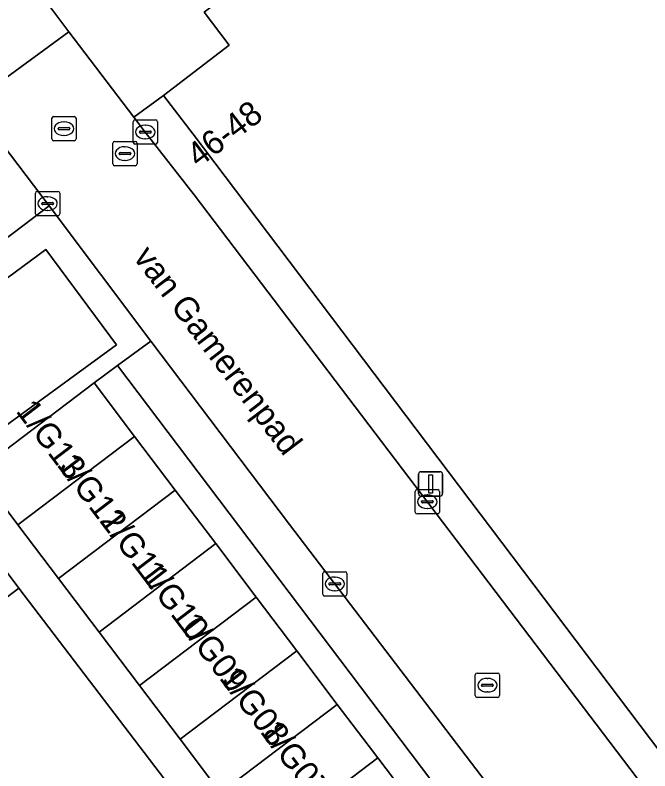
# Model space of a CAD drawing. Extents: x 160030 to 160839, y 385325 to 386450.
# Drawn here: x 160266.91 to 160293.06, y 385935.27 to 385966.37 of the extents above; entities that cross this region are included whole.
import ezdxf

# ---------------------------------------------------------------- set-up
doc = ezdxf.new("R2010")
doc.units = 0
for name, color, linetype in [('IMGEO_Erf', 7, 'Continuous'), ('IMGEO_Groenvoorziening', 7, 'Continuous'), ('IMGEO_Kolk', 7, 'Continuous'), ('IMGEO_Lichtmast', 7, 'Continuous'), ('IMGEO_Openbare_ruimte_label', 7, 'Continuous'), ('IMGEO_Pand', 7, 'Continuous'), ('IMGEO_Pand_nummerreeks', 7, 'Continuous'), ('IMGEO_Rijbaan_lokaal_open', 7, 'Continuous'), ('IMGEO_Rioolput', 7, 'Continuous'), ('IMGEO_Voetpad_open', 7, 'Continuous')]:
    doc.layers.add(name, color=color, linetype=linetype)

msp = doc.modelspace()

# ---------------------------------------------------------------- linework, layer by layer
at = {"layer": 'IMGEO_Erf'}
msp.add_lwpolyline([(160271.131, 385951.947), (160270.16, 385951.238), (160271.83, 385949.032), (160273.5, 385946.826), (160275.171, 385944.62), (160276.841, 385942.414), (160278.511, 385940.208), (160280.181, 385938.002), (160281.852, 385935.796), (160283.522, 385933.59), (160285.192, 385931.384), (160286.862, 385929.178), (160288.533, 385926.972), (160290.203, 385924.766), (160291.873, 385922.56), (160291.96, 385922.629), (160292.815, 385923.307)], close=True, dxfattribs=at)
msp.add_lwpolyline([(160274.513, 385933.022), (160267.063, 385942.785), (160262.194, 385939.095), (160257.405, 385935.465), (160252.615, 385931.834)], dxfattribs=at)
at = {"layer": 'IMGEO_Groenvoorziening'}
for points in [[(160268.311, 385958.528), (160261.172, 385953.121), (160264.176, 385949.153), (160265.353, 385947.599), (160270.16, 385951.238), (160271.131, 385951.947), (160272.504, 385952.949)], [(160271.086, 385952.807), (160265.969, 385949.077), (160263.052, 385952.951), (160268.169, 385956.728)], [(160263.052, 385952.951), (160265.969, 385949.077), (160271.086, 385952.807), (160268.169, 385956.728)]]:
    msp.add_lwpolyline(points, close=True, dxfattribs=at)
at = {"layer": 'IMGEO_Kolk'}
for p, q in [((160271.77, 385961.134), (160271.77, 385961.986)), ((160271.845, 385962.06), (160272.697, 385962.06)), ((160272.258, 385961.84), (160272.283, 385961.84)), ((160272.771, 385961.986), (160272.771, 385961.134)), ((160272.029, 385961.554), (160272.029, 385961.566)), ((160272.072, 385961.603), (160272.47, 385961.603)), ((160272.513, 385961.566), (160272.513, 385961.554)), ((160272.467, 385961.517), (160272.069, 385961.517)), ((160272.281, 385961.28), (160272.256, 385961.28)), ((160272.697, 385961.06), (160271.845, 385961.06)), ((160267.743, 385958.191), (160267.743, 385959.043)), ((160267.818, 385959.117), (160268.67, 385959.117)), ((160268.744, 385959.043), (160268.744, 385958.191)), ((160268.231, 385958.897), (160268.256, 385958.897)), ((160268.002, 385958.611), (160268.002, 385958.623)), ((160268.44, 385958.574), (160268.042, 385958.574)), ((160268.045, 385958.66), (160268.443, 385958.66)), ((160268.486, 385958.623), (160268.486, 385958.611)), ((160268.67, 385958.117), (160267.818, 385958.117)), ((160268.254, 385958.337), (160268.229, 385958.337)), ((160283.391, 385945.917), (160283.391, 385946.769)), ((160283.466, 385946.843), (160284.318, 385946.843)), ((160283.879, 385946.623), (160283.904, 385946.623)), ((160284.392, 385946.769), (160284.392, 385945.917)), ((160283.65, 385946.337), (160283.65, 385946.349)), ((160284.088, 385946.3), (160283.69, 385946.3)), ((160283.693, 385946.386), (160284.091, 385946.386)), ((160284.134, 385946.349), (160284.134, 385946.337)), ((160283.902, 385946.063), (160283.877, 385946.063)), ((160284.318, 385945.843), (160283.466, 385945.843)), ((160279.578, 385942.536), (160279.578, 385943.388)), ((160279.653, 385943.462), (160280.505, 385943.462)), ((160280.066, 385943.242), (160280.091, 385943.242)), ((160280.579, 385943.388), (160280.579, 385942.536)), ((160279.837, 385942.956), (160279.837, 385942.968)), ((160280.275, 385942.919), (160279.877, 385942.919)), ((160279.88, 385943.005), (160280.278, 385943.005)), ((160280.321, 385942.968), (160280.321, 385942.956)), ((160280.089, 385942.682), (160280.064, 385942.682)), ((160280.505, 385942.462), (160279.653, 385942.462))]:
    msp.add_line(p, q, dxfattribs=at)
for points in [[(160271.77, 385961.134), (160271.77, 385961.986)], [(160271.845, 385962.06), (160272.697, 385962.06)], [(160272.771, 385961.986), (160272.771, 385961.134)], [(160272.697, 385961.06), (160271.845, 385961.06)], [(160267.743, 385958.191), (160267.743, 385959.043)], [(160267.818, 385959.117), (160268.67, 385959.117)], [(160268.744, 385959.043), (160268.744, 385958.191)], [(160268.67, 385958.117), (160267.818, 385958.117)], [(160283.391, 385945.917), (160283.391, 385946.769)], [(160283.466, 385946.843), (160284.318, 385946.843)], [(160284.392, 385946.769), (160284.392, 385945.917)], [(160284.318, 385945.843), (160283.466, 385945.843)], [(160279.578, 385942.536), (160279.578, 385943.388)], [(160279.653, 385943.462), (160280.505, 385943.462)], [(160280.579, 385943.388), (160280.579, 385942.536)], [(160280.505, 385942.462), (160279.653, 385942.462)]]:
    msp.add_lwpolyline(points, dxfattribs=at)
for centre, radius, start, end in [((160271.847, 385961.984), 0.0765, 91.552, 178.448), ((160271.847, 385961.984), 0.0765, 91.552, 178.448), ((160272.695, 385961.984), 0.0765, 1.552, 88.448), ((160272.695, 385961.984), 0.0765, 1.552, 88.448), ((160272.069, 385961.563), 0.0403, 85.8775, 175.7526), ((160272.066, 385961.553), 0.0366, 178.938, 274.7102), ((160272.47, 385961.56), 0.043, 264.8664, 352.4533), ((160272.474, 385961.565), 0.0386, 1.7309, 96.639), ((160271.847, 385961.136), 0.0765, 181.552, 268.448), ((160271.847, 385961.136), 0.0765, 181.552, 268.448), ((160272.695, 385961.136), 0.0765, 271.552, 358.448), ((160272.695, 385961.136), 0.0765, 271.552, 358.448), ((160267.82, 385959.041), 0.0765, 91.552, 178.448), ((160267.82, 385959.041), 0.0765, 91.552, 178.448), ((160268.668, 385959.041), 0.0765, 1.552, 88.448), ((160268.668, 385959.041), 0.0765, 1.552, 88.448), ((160268.042, 385958.62), 0.0403, 85.8775, 175.7526), ((160268.039, 385958.61), 0.0366, 178.938, 274.7102), ((160268.443, 385958.617), 0.043, 264.8664, 352.4533), ((160268.447, 385958.622), 0.0386, 1.7309, 96.639), ((160267.82, 385958.193), 0.0765, 181.552, 268.448), ((160267.82, 385958.193), 0.0765, 181.552, 268.448), ((160268.668, 385958.193), 0.0765, 271.552, 358.448), ((160268.668, 385958.193), 0.0765, 271.552, 358.448), ((160283.468, 385946.767), 0.0765, 91.552, 178.448), ((160283.468, 385946.767), 0.0765, 91.552, 178.448), ((160284.316, 385946.767), 0.0765, 1.552, 88.448), ((160284.316, 385946.767), 0.0765, 1.552, 88.448), ((160283.69, 385946.346), 0.0403, 85.8775, 175.7526), ((160283.687, 385946.336), 0.0366, 178.938, 274.7102), ((160284.091, 385946.343), 0.043, 264.8664, 352.4533), ((160284.095, 385946.348), 0.0386, 1.7309, 96.639), ((160283.468, 385945.919), 0.0765, 181.552, 268.448), ((160283.468, 385945.919), 0.0765, 181.552, 268.448), ((160284.316, 385945.919), 0.0765, 271.552, 358.448), ((160284.316, 385945.919), 0.0765, 271.552, 358.448), ((160279.655, 385943.386), 0.0765, 91.552, 178.448), ((160279.655, 385943.386), 0.0765, 91.552, 178.448), ((160280.503, 385943.386), 0.0765, 1.552, 88.448), ((160280.503, 385943.386), 0.0765, 1.552, 88.448), ((160279.877, 385942.965), 0.0403, 85.8775, 175.7526), ((160279.874, 385942.955), 0.0366, 178.938, 274.7102), ((160280.278, 385942.962), 0.043, 264.8664, 352.4533), ((160280.282, 385942.967), 0.0386, 1.7309, 96.639), ((160279.655, 385942.538), 0.0765, 181.552, 268.448), ((160279.655, 385942.538), 0.0765, 181.552, 268.448), ((160280.503, 385942.538), 0.0765, 271.552, 358.448), ((160280.503, 385942.538), 0.0765, 271.552, 358.448)]:
    msp.add_arc(centre, radius, start, end, dxfattribs=at)
for centre, major_axis, ratio, start_param, end_param in [((160272.257, 385961.56), (-0.387, 0.002), 0.722429, 4.712389, 7.853982), ((160272.282, 385961.56), (-0.39, 0.002), 0.717154, 1.570796, 4.712389), ((160268.23, 385958.617), (-0.387, 0.002), 0.722429, 4.712389, 7.853982), ((160268.255, 385958.617), (-0.39, 0.002), 0.717154, 1.570796, 4.712389), ((160283.878, 385946.343), (-0.387, 0.002), 0.722429, 4.712389, 7.853982), ((160283.903, 385946.343), (-0.39, 0.002), 0.717154, 1.570796, 4.712389), ((160280.065, 385942.962), (-0.387, 0.002), 0.722429, 4.712389, 7.853982), ((160280.09, 385942.962), (-0.39, 0.002), 0.717154, 1.570796, 4.712389)]:
    msp.add_ellipse(centre, major_axis=major_axis, ratio=ratio, start_param=start_param, end_param=end_param, dxfattribs=at)
at = {"layer": 'IMGEO_Lichtmast'}
for p, q in [((160283.626, 385947.577), (160284.416, 385947.577)), ((160284.416, 385947.577), (160283.626, 385947.577)), ((160283.526, 385946.677), (160283.526, 385947.477)), ((160283.526, 385947.477), (160283.526, 385946.677)), ((160284.516, 385947.477), (160284.516, 385946.677)), ((160284.516, 385946.677), (160284.516, 385947.477)), ((160284.416, 385946.577), (160283.626, 385946.577)), ((160283.626, 385946.577), (160284.416, 385946.577))]:
    msp.add_line(p, q, dxfattribs=at)
msp.add_lwpolyline([(160283.946, 385947.452), (160284.096, 385947.452), (160284.096, 385946.702), (160283.946, 385946.702), (160283.946, 385947.452)], dxfattribs=at)
for centre, start, end in [((160283.626, 385947.477), 90, 180), ((160283.626, 385947.477), 90, 180), ((160284.416, 385947.477), 0, 90), ((160284.416, 385947.477), 360, 90), ((160283.626, 385946.677), 180, 270), ((160283.626, 385946.677), 180, 270), ((160284.416, 385946.677), 270, 0), ((160284.416, 385946.677), 270, 0)]:
    msp.add_arc(centre, 0.1, start, end, dxfattribs=at)
at = {"layer": 'IMGEO_Pand'}
msp.add_lwpolyline([(160296.888, 385963.664), (160292.909, 385968.884), (160291.169, 385967.555), (160288.295, 385971.358), (160290.035, 385972.688), (160287.372, 385976.172), (160280.698, 385971.072), (160281.211, 385970.387), (160278.649, 385968.442), (160278.135, 385969.119), (160274.691, 385966.501), (160275.731, 385965.132), (160273.026, 385963.07), (160274.238, 385961.479), (160300.528, 385926.728)], dxfattribs=at)
for points in [[(160267.023, 385945.393), (160271.83, 385949.032), (160270.16, 385951.238), (160265.353, 385947.599)], [(160267.023, 385945.393), (160268.694, 385943.187), (160273.5, 385946.826), (160271.83, 385949.032)], [(160262.944, 385948.218), (160258.076, 385944.528), (160262.194, 385939.095), (160267.063, 385942.785), (160265.965, 385944.234), (160264.121, 385946.666)], [(160275.171, 385944.62), (160273.5, 385946.826), (160268.694, 385943.187), (160270.364, 385940.981)], [(160270.364, 385940.981), (160272.034, 385938.775), (160276.841, 385942.414), (160275.171, 385944.62)], [(160272.034, 385938.775), (160273.704, 385936.569), (160278.511, 385940.208), (160276.841, 385942.414)], [(160280.181, 385938.002), (160278.511, 385940.208), (160273.704, 385936.569), (160275.375, 385934.363)], [(160275.375, 385934.363), (160277.045, 385932.157), (160281.852, 385935.796), (160280.181, 385938.002)], [(160277.045, 385932.157), (160278.715, 385929.951), (160283.522, 385933.59), (160281.852, 385935.796)]]:
    msp.add_lwpolyline(points, close=True, dxfattribs=at)
at = {"layer": 'IMGEO_Rijbaan_lokaal_open'}
for points in [[(160264.446, 385963.608), (160265.109, 385962.726), (160266.287, 385963.609), (160269.121, 385965.683), (160268.378, 385966.677)], [(160274.289, 385958.969), (160272.271, 385961.56), (160271.801, 385962.176), (160269.121, 385965.683), (160266.287, 385963.609), (160265.109, 385962.726), (160268.311, 385958.528), (160272.504, 385952.949), (160278.21, 385945.409), (160294.227, 385924.426), (160296.595, 385921.073)], [(160300.632, 385924.328), (160300.493, 385924.507), (160299.426, 385925.902), (160274.289, 385958.969)]]:
    msp.add_lwpolyline(points, dxfattribs=at)
at = {"layer": 'IMGEO_Rioolput'}
for p, q in [((160268.494, 385962.2), (160269.346, 385962.2)), ((160268.419, 385961.274), (160268.419, 385962.126)), ((160268.907, 385961.98), (160268.932, 385961.98)), ((160269.42, 385962.126), (160269.42, 385961.274)), ((160268.678, 385961.694), (160268.678, 385961.706)), ((160269.116, 385961.657), (160268.718, 385961.657)), ((160268.721, 385961.743), (160269.119, 385961.743)), ((160269.162, 385961.706), (160269.162, 385961.694)), ((160268.93, 385961.42), (160268.905, 385961.42)), ((160269.346, 385961.2), (160268.494, 385961.2)), ((160270.931, 385960.249), (160270.931, 385961.101)), ((160271.006, 385961.175), (160271.858, 385961.175)), ((160271.419, 385960.955), (160271.444, 385960.955)), ((160271.932, 385961.101), (160271.932, 385960.249)), ((160271.19, 385960.669), (160271.19, 385960.681)), ((160271.628, 385960.632), (160271.23, 385960.632)), ((160271.233, 385960.718), (160271.631, 385960.718)), ((160271.674, 385960.681), (160271.674, 385960.669)), ((160271.442, 385960.395), (160271.417, 385960.395)), ((160271.858, 385960.175), (160271.006, 385960.175)), ((160285.866, 385938.366), (160285.866, 385939.218)), ((160285.941, 385939.292), (160286.793, 385939.292)), ((160286.867, 385939.218), (160286.867, 385938.366)), ((160286.168, 385938.835), (160286.566, 385938.835)), ((160286.354, 385939.072), (160286.379, 385939.072)), ((160286.125, 385938.786), (160286.125, 385938.798)), ((160286.563, 385938.749), (160286.165, 385938.749)), ((160286.377, 385938.512), (160286.352, 385938.512)), ((160286.609, 385938.798), (160286.609, 385938.786)), ((160286.793, 385938.292), (160285.941, 385938.292))]:
    msp.add_line(p, q, dxfattribs=at)
for points in [[(160268.494, 385962.2), (160269.346, 385962.2)], [(160268.419, 385961.274), (160268.419, 385962.126)], [(160269.42, 385962.126), (160269.42, 385961.274)], [(160269.346, 385961.2), (160268.494, 385961.2)], [(160270.931, 385960.249), (160270.931, 385961.101)], [(160271.006, 385961.175), (160271.858, 385961.175)], [(160271.932, 385961.101), (160271.932, 385960.249)], [(160271.858, 385960.175), (160271.006, 385960.175)], [(160285.866, 385938.366), (160285.866, 385939.218)], [(160285.941, 385939.292), (160286.793, 385939.292)], [(160286.867, 385939.218), (160286.867, 385938.366)], [(160286.793, 385938.292), (160285.941, 385938.292)]]:
    msp.add_lwpolyline(points, dxfattribs=at)
for centre, radius, start, end in [((160268.496, 385962.124), 0.0765, 91.552, 178.448), ((160268.496, 385962.124), 0.0765, 91.552, 178.448), ((160269.344, 385962.124), 0.0765, 1.552, 88.448), ((160269.344, 385962.124), 0.0765, 1.552, 88.448), ((160268.718, 385961.703), 0.0403, 85.8775, 175.7526), ((160268.715, 385961.693), 0.0366, 178.938, 274.7102), ((160269.119, 385961.7), 0.043, 264.8664, 352.4533), ((160269.123, 385961.705), 0.0386, 1.7309, 96.639), ((160268.496, 385961.276), 0.0765, 181.552, 268.448), ((160268.496, 385961.276), 0.0765, 181.552, 268.448), ((160269.344, 385961.276), 0.0765, 271.552, 358.448), ((160269.344, 385961.276), 0.0765, 271.552, 358.448), ((160271.008, 385961.099), 0.0765, 91.552, 178.448), ((160271.008, 385961.099), 0.0765, 91.552, 178.448), ((160271.856, 385961.099), 0.0765, 1.552, 88.448), ((160271.856, 385961.099), 0.0765, 1.552, 88.448), ((160271.23, 385960.678), 0.0403, 85.8775, 175.7526), ((160271.227, 385960.668), 0.0366, 178.938, 274.7102), ((160271.631, 385960.675), 0.043, 264.8664, 352.4533), ((160271.635, 385960.68), 0.0386, 1.7309, 96.639), ((160271.008, 385960.251), 0.0765, 181.552, 268.448), ((160271.008, 385960.251), 0.0765, 181.552, 268.448), ((160271.856, 385960.251), 0.0765, 271.552, 358.448), ((160271.856, 385960.251), 0.0765, 271.552, 358.448), ((160285.943, 385939.216), 0.0765, 91.552, 178.448), ((160285.943, 385939.216), 0.0765, 91.552, 178.448), ((160286.791, 385939.216), 0.0765, 1.552, 88.448), ((160286.791, 385939.216), 0.0765, 1.552, 88.448), ((160286.165, 385938.795), 0.0403, 85.8775, 175.7526), ((160286.57, 385938.797), 0.0386, 1.7309, 96.639), ((160286.162, 385938.785), 0.0366, 178.938, 274.7102), ((160286.566, 385938.792), 0.043, 264.8664, 352.4533), ((160285.943, 385938.368), 0.0765, 181.552, 268.448), ((160285.943, 385938.368), 0.0765, 181.552, 268.448), ((160286.791, 385938.368), 0.0765, 271.552, 358.448), ((160286.791, 385938.368), 0.0765, 271.552, 358.448)]:
    msp.add_arc(centre, radius, start, end, dxfattribs=at)
for centre, major_axis, ratio, start_param, end_param in [((160268.906, 385961.7), (-0.387, 0.002), 0.722429, 4.712389, 7.853982), ((160268.931, 385961.7), (-0.39, 0.002), 0.717154, 1.570796, 4.712389), ((160271.418, 385960.675), (-0.387, 0.002), 0.722429, 4.712389, 7.853982), ((160271.443, 385960.675), (-0.39, 0.002), 0.717154, 1.570796, 4.712389), ((160286.353, 385938.792), (-0.387, 0.002), 0.722429, 4.712389, 7.853982), ((160286.378, 385938.792), (-0.39, 0.002), 0.717154, 1.570796, 4.712389)]:
    msp.add_ellipse(centre, major_axis=major_axis, ratio=ratio, start_param=start_param, end_param=end_param, dxfattribs=at)
at = {"layer": 'IMGEO_Voetpad_open'}
for points in [[(160268.378, 385966.677), (160269.121, 385965.683), (160271.801, 385962.176), (160273.026, 385963.07), (160275.731, 385965.132), (160274.691, 385966.501), (160278.135, 385969.119), (160278.649, 385968.442), (160281.211, 385970.387), (160280.698, 385971.072), (160287.372, 385976.172)], [(160259.939, 385952.187), (160261.172, 385953.121), (160268.311, 385958.528), (160265.109, 385962.726), (160264.446, 385963.608)]]:
    msp.add_lwpolyline(points, dxfattribs=at)
for points in [[(160274.238, 385961.479), (160273.026, 385963.07), (160271.801, 385962.176), (160272.271, 385961.56), (160274.289, 385958.969), (160299.426, 385925.902), (160300.528, 385926.728)], [(160292.815, 385923.307), (160294.227, 385924.426), (160278.21, 385945.409), (160272.504, 385952.949), (160271.131, 385951.947)], [(160277.045, 385932.157), (160275.375, 385934.363), (160273.704, 385936.569), (160272.034, 385938.775), (160270.364, 385940.981), (160268.694, 385943.187), (160267.023, 385945.393), (160265.353, 385947.599), (160264.121, 385946.666), (160265.965, 385944.234), (160267.063, 385942.785), (160274.513, 385933.022), (160275.43, 385931.82), (160283.21, 385921.624), (160284.24, 385920.265), (160285.917, 385918.052), (160287.066, 385918.921), (160285.396, 385921.127), (160283.726, 385923.333), (160282.056, 385925.539), (160280.385, 385927.745), (160278.715, 385929.951)]]:
    msp.add_lwpolyline(points, close=True, dxfattribs=at)

# ---------------------------------------------------------------- texts
at = {"layer": 'IMGEO_Openbare_ruimte_label'}
msp.add_text('van Gamerenpad', height=1, rotation=307.2823, dxfattribs=at).set_placement((160271.742, 385956.395))
at = {"layer": 'IMGEO_Pand_nummerreeks'}
for s, rotation, p in [('46-48', 37.1162, (160274.462, 385960.067)), ('1/G13', 307.3301, (160266.907, 385950.07)), ('1/G12', 307.3301, (160268.59, 385947.863)), ('1/G11', 307.3301, (160270.347, 385945.559)), ('1/G10', 307.3301, (160271.969, 385943.432)), ('1/G09', 307.3301, (160273.597, 385941.298)), ('1/G08', 307.3301, (160275.287, 385939.081)), ('1/G07', 307.3301, (160276.972, 385936.871))]:
    msp.add_text(s, height=1, rotation=rotation, dxfattribs=at).set_placement(p)

doc.saveas('drawing.dxf')
